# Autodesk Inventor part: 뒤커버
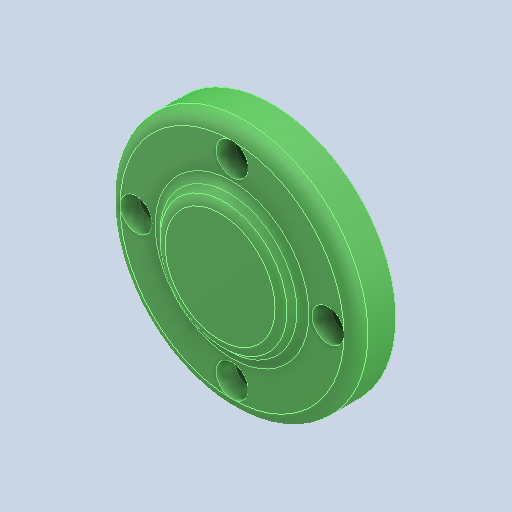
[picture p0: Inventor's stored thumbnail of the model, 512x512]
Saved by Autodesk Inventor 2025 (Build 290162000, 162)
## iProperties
Created: 2024-07
Part Number: 뒤커버
Material: 알루미늄 6061
Document SubType Name: Modeling
Designer: Administrator
Density: 2.71 g/cm^3
Appearance: 기본값
Author: jhkim
Sending System: Autodesk Inventor 2025
Preprocessor: ST-DEVELOPER v20
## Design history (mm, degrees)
feature "솔리드1"
node "솔리드2"
